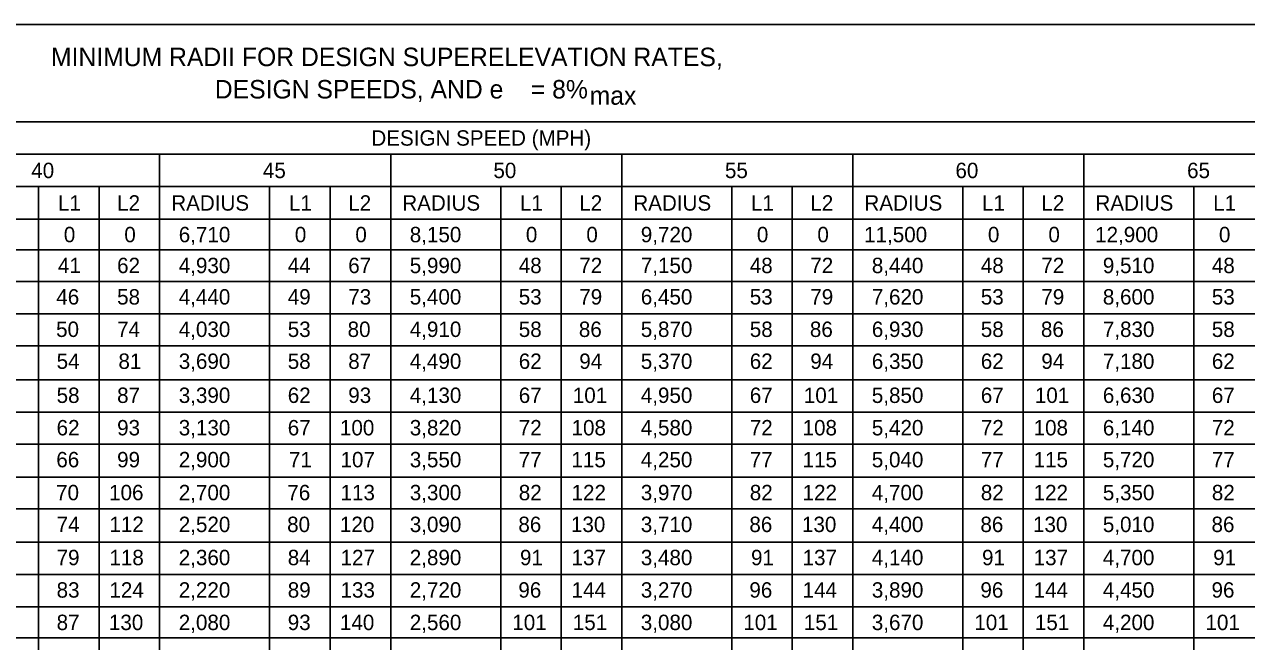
# Model space of a CAD drawing. Extents: x -404.8 to -373.6, y -458.1 to -437.7.
# Drawn here: x -398.05 to -386.16, y -451.76 to -445.75 of the extents above; entities that cross this region are included whole.
import ezdxf

# ---------------------------------------------------------------- set-up
doc = ezdxf.new("R2010")
doc.units = 0
doc.layers.add('Common-Notes', color=7, linetype='Continuous')
doc.layers.add('Level 4', color=7, linetype='Continuous')

msp = doc.modelspace()

# ---------------------------------------------------------------- linework, layer by layer
at = {"layer": 'Level 4'}
for p, q in [((-404.161, -445.747), (-383.242, -445.747)), ((-404.161, -446.696), (-383.242, -446.696)), ((-403.485, -447.012), (-383.242, -447.012)), ((-396.737, -447.012), (-396.737, -457.744)), ((-394.488, -447.012), (-394.488, -457.744)), ((-392.239, -447.012), (-392.239, -457.744)), ((-389.99, -447.012), (-389.99, -457.744)), ((-387.741, -447.012), (-387.741, -457.744)), ((-403.485, -447.328), (-383.242, -447.328)), ((-397.915, -447.328), (-397.915, -457.744)), ((-397.326, -447.328), (-397.326, -457.744)), ((-395.666, -447.328), (-395.666, -457.744)), ((-395.077, -447.328), (-395.077, -457.744)), ((-393.417, -447.328), (-393.417, -457.744)), ((-392.828, -447.328), (-392.828, -457.744)), ((-391.168, -447.328), (-391.168, -457.744)), ((-390.579, -447.328), (-390.579, -457.744)), ((-388.919, -447.328), (-388.919, -457.744)), ((-388.33, -447.328), (-388.33, -457.744)), ((-386.67, -447.328), (-386.67, -457.744)), ((-404.161, -447.645), (-383.242, -447.645)), ((-404.161, -447.945), (-383.242, -447.945)), ((-404.161, -448.251), (-383.242, -448.251)), ((-404.161, -448.567), (-383.242, -448.567)), ((-404.161, -448.878), (-383.242, -448.878)), ((-404.161, -449.21), (-383.242, -449.21)), ((-404.161, -449.526), (-383.242, -449.526)), ((-404.161, -449.837), (-383.242, -449.837)), ((-404.161, -450.159), (-383.242, -450.159)), ((-404.161, -450.469), (-383.242, -450.469)), ((-404.161, -450.791), (-383.242, -450.791)), ((-404.161, -451.107), (-383.242, -451.107)), ((-404.161, -451.424), (-383.242, -451.424)), ((-404.161, -451.724), (-383.242, -451.724))]:
    msp.add_line(p, q, dxfattribs=at)

# ---------------------------------------------------------------- texts
at = {"layer": 'Common-Notes'}
for s, height, p in [('MINIMUM RADII FOR DESIGN SUPERELEVATION RATES,', 0.18, (-397.795, -446.154)), ('DESIGN SPEEDS, AND e    = 8%', 0.18, (-396.2, -446.469)), ('DESIGN SPEED (MPH)', 0.15, (-394.676, -446.929)), ('40', 0.15, (-397.987, -447.245)), ('50', 0.15, (-393.488, -447.245)), ('60', 0.15, (-388.99, -447.245)), ('65', 0.15, (-386.735, -447.245)), ('45', 0.15, (-395.732, -447.245)), ('55', 0.15, (-391.234, -447.245)), ('L1', 0.15, (-397.727, -447.562)), ('L2', 0.15, (-397.151, -447.562)), ('RADIUS', 0.15, (-396.624, -447.562)), ('L1', 0.15, (-395.478, -447.562)), ('L2', 0.15, (-394.901, -447.562)), ('RADIUS', 0.15, (-394.375, -447.562)), ('L1', 0.15, (-393.229, -447.562)), ('L2', 0.15, (-392.652, -447.562)), ('RADIUS', 0.15, (-392.126, -447.562)), ('L1', 0.15, (-390.98, -447.562)), ('L2', 0.15, (-390.403, -447.562)), ('RADIUS', 0.15, (-389.876, -447.562)), ('L1', 0.15, (-388.731, -447.562)), ('L2', 0.15, (-388.154, -447.562)), ('RADIUS', 0.15, (-387.627, -447.562)), ('L1', 0.15, (-386.481, -447.562)), ('0', 0.15, (-397.67, -447.87)), ('0', 0.15, (-397.081, -447.87)), ('6,710', 0.15, (-396.551, -447.87)), ('0', 0.15, (-395.421, -447.87)), ('0', 0.15, (-394.832, -447.87)), ('8,150', 0.15, (-394.302, -447.87)), ('0', 0.15, (-393.172, -447.87)), ('0', 0.15, (-392.583, -447.87)), ('9,720', 0.15, (-392.053, -447.87)), ('0', 0.15, (-390.923, -447.87)), ('0', 0.15, (-390.334, -447.87)), ('11,500', 0.15, (-389.879, -447.87)), ('0', 0.15, (-388.674, -447.87)), ('0', 0.15, (-388.085, -447.87)), ('12,900', 0.15, (-387.63, -447.87)), ('0', 0.15, (-386.425, -447.87)), ('41', 0.15, (-397.727, -448.171)), ('62', 0.15, (-397.151, -448.171)), ('4,930', 0.15, (-396.551, -448.171)), ('44', 0.15, (-395.49, -448.171)), ('67', 0.15, (-394.901, -448.171)), ('5,990', 0.15, (-394.302, -448.171)), ('48', 0.15, (-393.241, -448.171)), ('72', 0.15, (-392.652, -448.171)), ('7,150', 0.15, (-392.053, -448.171)), ('48', 0.15, (-390.992, -448.171)), ('72', 0.15, (-390.403, -448.171)), ('8,440', 0.15, (-389.804, -448.171)), ('48', 0.15, (-388.743, -448.171)), ('72', 0.15, (-388.154, -448.171)), ('9,510', 0.15, (-387.555, -448.171)), ('48', 0.15, (-386.494, -448.171)), ('46', 0.15, (-397.743, -448.477)), ('58', 0.15, (-397.151, -448.477)), ('4,440', 0.15, (-396.551, -448.477)), ('49', 0.15, (-395.49, -448.477)), ('73', 0.15, (-394.901, -448.477)), ('5,400', 0.15, (-394.302, -448.477)), ('53', 0.15, (-393.241, -448.477)), ('79', 0.15, (-392.652, -448.477)), ('6,450', 0.15, (-392.053, -448.477)), ('53', 0.15, (-390.992, -448.477)), ('79', 0.15, (-390.403, -448.477)), ('7,620', 0.15, (-389.804, -448.477)), ('53', 0.15, (-388.743, -448.477)), ('79', 0.15, (-388.154, -448.477)), ('8,600', 0.15, (-387.555, -448.477)), ('53', 0.15, (-386.494, -448.477)), ('50', 0.15, (-397.745, -448.793)), ('4,030', 0.15, (-396.551, -448.793)), ('53', 0.15, (-395.49, -448.793)), ('80', 0.15, (-394.907, -448.793)), ('4,910', 0.15, (-394.302, -448.793)), ('58', 0.15, (-393.241, -448.793)), ('86', 0.15, (-392.656, -448.793)), ('5,870', 0.15, (-392.053, -448.793)), ('58', 0.15, (-390.992, -448.793)), ('86', 0.15, (-390.407, -448.793)), ('6,930', 0.15, (-389.804, -448.793)), ('58', 0.15, (-388.743, -448.793)), ('86', 0.15, (-388.158, -448.793)), ('7,830', 0.15, (-387.555, -448.793)), ('58', 0.15, (-386.494, -448.793)), ('74', 0.15, (-397.151, -448.793)), ('54', 0.15, (-397.74, -449.104)), ('81', 0.15, (-397.138, -449.104)), ('3,690', 0.15, (-396.551, -449.104)), ('58', 0.15, (-395.49, -449.104)), ('87', 0.15, (-394.901, -449.104)), ('4,490', 0.15, (-394.302, -449.104)), ('62', 0.15, (-393.241, -449.104)), ('94', 0.15, (-392.652, -449.104)), ('5,370', 0.15, (-392.053, -449.104)), ('62', 0.15, (-390.992, -449.104)), ('94', 0.15, (-390.403, -449.104)), ('6,350', 0.15, (-389.804, -449.104)), ('62', 0.15, (-388.743, -449.104)), ('94', 0.15, (-388.154, -449.104)), ('7,180', 0.15, (-387.555, -449.104)), ('62', 0.15, (-386.494, -449.104)), ('58', 0.15, (-397.74, -449.436)), ('87', 0.15, (-397.151, -449.436)), ('3,390', 0.15, (-396.551, -449.436)), ('62', 0.15, (-395.49, -449.436)), ('93', 0.15, (-394.901, -449.436)), ('4,130', 0.15, (-394.302, -449.436)), ('67', 0.15, (-393.241, -449.436)), ('101', 0.15, (-392.715, -449.436)), ('4,950', 0.15, (-392.053, -449.436)), ('67', 0.15, (-390.992, -449.436)), ('101', 0.15, (-390.466, -449.436)), ('5,850', 0.15, (-389.804, -449.436)), ('67', 0.15, (-388.743, -449.436)), ('101', 0.15, (-388.217, -449.436)), ('6,630', 0.15, (-387.555, -449.436)), ('67', 0.15, (-386.494, -449.436)), ('62', 0.15, (-397.74, -449.752)), ('93', 0.15, (-397.151, -449.752)), ('3,130', 0.15, (-396.551, -449.752)), ('67', 0.15, (-395.49, -449.752)), ('100', 0.15, (-394.982, -449.752)), ('3,820', 0.15, (-394.302, -449.752)), ('72', 0.15, (-393.241, -449.752)), ('108', 0.15, (-392.727, -449.752)), ('4,580', 0.15, (-392.053, -449.752)), ('72', 0.15, (-390.992, -449.752)), ('108', 0.15, (-390.478, -449.752)), ('5,420', 0.15, (-389.804, -449.752)), ('72', 0.15, (-388.743, -449.752)), ('108', 0.15, (-388.229, -449.752)), ('6,140', 0.15, (-387.555, -449.752)), ('72', 0.15, (-386.494, -449.752)), ('66', 0.15, (-397.743, -450.063)), ('99', 0.15, (-397.151, -450.063)), ('2,900', 0.15, (-396.551, -450.063)), ('71', 0.15, (-395.478, -450.063)), ('107', 0.15, (-394.976, -450.063)), ('3,550', 0.15, (-394.302, -450.063)), ('77', 0.15, (-393.241, -450.063)), ('115', 0.15, (-392.728, -450.063)), ('4,250', 0.15, (-392.053, -450.063)), ('77', 0.15, (-390.992, -450.063)), ('115', 0.15, (-390.478, -450.063)), ('5,040', 0.15, (-389.804, -450.063)), ('77', 0.15, (-388.743, -450.063)), ('115', 0.15, (-388.229, -450.063)), ('5,720', 0.15, (-387.555, -450.063)), ('77', 0.15, (-386.494, -450.063)), ('70', 0.15, (-397.745, -450.384)), ('106', 0.15, (-397.229, -450.384)), ('2,700', 0.15, (-396.551, -450.384)), ('76', 0.15, (-395.494, -450.384)), ('113', 0.15, (-394.976, -450.384)), ('3,300', 0.15, (-394.302, -450.384)), ('82', 0.15, (-393.241, -450.384)), ('122', 0.15, (-392.727, -450.384)), ('3,970', 0.15, (-392.053, -450.384)), ('82', 0.15, (-390.992, -450.384)), ('122', 0.15, (-390.478, -450.384)), ('4,700', 0.15, (-389.804, -450.384)), ('82', 0.15, (-388.743, -450.384)), ('122', 0.15, (-388.229, -450.384)), ('5,350', 0.15, (-387.555, -450.384)), ('82', 0.15, (-386.494, -450.384)), ('74', 0.15, (-397.74, -450.694)), ('112', 0.15, (-397.226, -450.694)), ('2,520', 0.15, (-396.551, -450.694)), ('80', 0.15, (-395.496, -450.694)), ('120', 0.15, (-394.982, -450.694)), ('3,090', 0.15, (-394.302, -450.694)), ('86', 0.15, (-393.245, -450.694)), ('130', 0.15, (-392.733, -450.694)), ('3,710', 0.15, (-392.053, -450.694)), ('86', 0.15, (-390.996, -450.694)), ('130', 0.15, (-390.484, -450.694)), ('4,400', 0.15, (-389.804, -450.694)), ('86', 0.15, (-388.747, -450.694)), ('130', 0.15, (-388.235, -450.694)), ('5,010', 0.15, (-387.555, -450.694)), ('86', 0.15, (-386.497, -450.694)), ('79', 0.15, (-397.74, -451.017)), ('118', 0.15, (-397.226, -451.017)), ('2,360', 0.15, (-396.551, -451.017)), ('84', 0.15, (-395.49, -451.017)), ('127', 0.15, (-394.976, -451.017)), ('2,890', 0.15, (-394.302, -451.017)), ('91', 0.15, (-393.229, -451.017)), ('137', 0.15, (-392.727, -451.017)), ('3,480', 0.15, (-392.053, -451.017)), ('91', 0.15, (-390.98, -451.017)), ('137', 0.15, (-390.478, -451.017)), ('4,140', 0.15, (-389.804, -451.017)), ('91', 0.15, (-388.731, -451.017)), ('137', 0.15, (-388.229, -451.017)), ('4,700', 0.15, (-387.555, -451.017)), ('91', 0.15, (-386.481, -451.017)), ('83', 0.15, (-397.74, -451.333)), ('124', 0.15, (-397.226, -451.333)), ('2,220', 0.15, (-396.551, -451.333)), ('89', 0.15, (-395.49, -451.333)), ('133', 0.15, (-394.976, -451.333)), ('2,720', 0.15, (-394.302, -451.333)), ('96', 0.15, (-393.245, -451.333)), ('144', 0.15, (-392.727, -451.333)), ('3,270', 0.15, (-392.053, -451.333)), ('96', 0.15, (-390.996, -451.333)), ('144', 0.15, (-390.478, -451.333)), ('3,890', 0.15, (-389.804, -451.333)), ('96', 0.15, (-388.747, -451.333)), ('144', 0.15, (-388.229, -451.333)), ('4,450', 0.15, (-387.555, -451.333)), ('96', 0.15, (-386.497, -451.333)), ('87', 0.15, (-397.74, -451.649)), ('130', 0.15, (-397.231, -451.649)), ('2,080', 0.15, (-396.551, -451.649)), ('93', 0.15, (-395.49, -451.649)), ('140', 0.15, (-394.982, -451.649)), ('2,560', 0.15, (-394.302, -451.649)), ('101', 0.15, (-393.304, -451.649)), ('3,080', 0.15, (-392.053, -451.649)), ('101', 0.15, (-391.055, -451.649)), ('3,670', 0.15, (-389.804, -451.649)), ('101', 0.15, (-388.806, -451.649)), ('4,200', 0.15, (-387.555, -451.649)), ('101', 0.15, (-386.556, -451.649)), ('151', 0.15, (-392.715, -451.649)), ('151', 0.15, (-390.466, -451.649)), ('151', 0.15, (-388.217, -451.649))]:
    msp.add_text(s, height=height, dxfattribs=at).set_placement(p)
at = {"layer": 'Level 4'}
msp.add_text('max', height=0.18, dxfattribs=at).set_placement((-392.551, -446.53))

doc.saveas('drawing.dxf')
